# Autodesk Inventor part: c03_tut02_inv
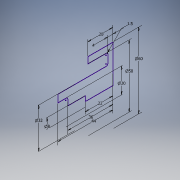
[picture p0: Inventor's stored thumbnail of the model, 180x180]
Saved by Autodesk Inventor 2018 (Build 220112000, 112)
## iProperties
Created: 2017-04
Part Number: c03_tut02_inv
Material: Generic
Document SubType Name: Modeling
Designer: CADCIM 00
Density: 1 g/cm^3
Appearance: Default
Author: CADCIM 00
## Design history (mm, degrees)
sketch "Sketch1"
  geometry: L1 (0, 0)-(-22, 0); L2 (-22, 0)-(-22, 4); L3 (-22, 4)-(-36, 4); L4 (-36, 4)-(-36, 8.5); L5 (-37.5, 10)-(-44, 10); L6 (-44, 10)-(-44, 16); L7 (-44, 16)-(-5.5, 16); L8 (-4, 17.5)-(-4, 23.5); L9 (-5.5, 25)-(-20, 25); L10 (-20, 25)-(-20, 30); L11 (-20, 30)-(0, 30); L12 (0, 30)-(0, 0); A1 r 1.5 centre (-5.5, 23.5) between (-4, 23.5) and (-5.5, 25); A2 r 1.5 centre (-37.5, 8.5) between (-36, 8.5) and (-37.5, 10); A3 r 1.5 centre (-5.5, 17.5) between (-5.5, 16) and (-4, 17.5)
  constraints: 24 end point, 11 perpendicular, 6 point on circle, 6 tangent, 3 centre point, 2 equal radius, 1 horizontal
  dimensions: "d0" = 8 diameter of L3 L1; "d1" = 20 diameter of L5 L1; "d2" = 32 diameter of L7 L1; "d3" = 50 diameter of L9 L1; "d4" = 60 diameter of L11 L1; "d5" = 4 distance between parallel lines of L8 L12; "d6" = 20 distance of L10.end L11.end; "d7" = 22 distance of L1.start L1.end; "d9" = 36 distance between parallel lines of L4 L12; "d10" = 44 distance between parallel lines of L12 L6; "d11" = 1.5 radius of A1
